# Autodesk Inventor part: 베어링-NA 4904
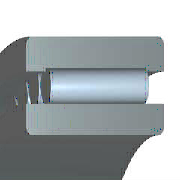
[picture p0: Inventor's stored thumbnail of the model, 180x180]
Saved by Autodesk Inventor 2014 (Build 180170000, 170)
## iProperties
IsCustomPart: 1
Company: 한국ATC센터
Created: 2009-02
Part Number: 베어링-NA 4904
Material: 강, 연강
Description: 니들 롤러 베어링 - 경계 치수 및 공차
Document SubType Name: Modeling
Standard: KS B 2029
Designer: KYOUNG IL JANG
Standards Organization: KS
Language: ko-KR
Size Designation: NA 4904 - 20 x 37 x 17
Categories: <MemberInstance><Categories><Category DisplayName="샤프트 부품" InternalName="7f7aeb1f-a693-4053-b835-cee3144e0d98" Mnemonic="SHFT"><Category DisplayName="베어링" Inter
Density: 7.86 g/cm^3
Mass: 73.0306 g
Surface Area: 90.2463 cm^2
Volume: 9.29143 cm^3
Vendor: CBT Solutions
Appearance: 강철
Author: KYOUNG IL JANG
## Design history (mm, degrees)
sketch "스케치"
  geometry: L1 (2.429, 16)-(14.571, 16); L2 (14.571, 16)-(14.571, 12.5); L3 (17, 12.5)-(0, 12.5); L4 (2.429, 12.5)-(2.429, 16); L5 (2.429, 14.25)-(14.571, 14.25); L6 (8.5, 14.25)-(8.5, 12.5); L7 (0, 10)-(17, 10); L8 (0, 18.5)-(17, 18.5); L9 (17, 10)-(17, 12.5); L10 (17, 15.65)-(17, 18.5); L11 (2.429, 15.65)-(0, 15.65); L12 (14.571, 15.65)-(17, 15.65); L13 (-6, 0)-(36, 0) reference; L14 (0, -1.9)-(0, 14.9) reference
  constraints: 24 end point, 8 point on line, 3 midpoint, 3 parallel, 3 perpendicular, 2 symmetric about line, 1 horizontal, 1 other
  dimensions: "d6" = 20 diameter of L7 L13 (= WD); "d7" = 25 diameter of L3 L13 (= KID1); "d8" = 37 diameter of L8 L13 (= BD); "d9" = 28.5 diameter of L6.start L13 (= 0.5 x WD + 0.5 x BD); "d10" = 31.3 diameter of L12 L13 (= 0.9 x BD + 0.9 x WD - 0.8 x KID1); "d11" = 32 diameter of L1 L13 (= BD + WD - KID1); "d12" = 2.42857 distance between parallel lines of L14 L4 (= 0.142857 x KB); "d13" = 17 distance between parallel lines of L14 L9 (= KB); "d14" = 14.57143 distance between parallel lines of L14 L2 (= 0.857143 x KB)
revolve "본체" stored, may be unused: angle "d17" = 90 deg
revolve "롤러" stored, may be unused: angle "d18" = 90 deg
pattern_circular "IDS_ARRAYROLLER[SIMPL:T]" dims angle "d2" = 360 deg
body "Solid1"
fillet "모깎기1" dims "d0" = 0.3 (= KRS)
other parameters: "WD" = 20 [user parameter; used in 6 equation terms], "BD" = 37 [user parameter; used in 6 equation terms], "KB" = 17 [user parameter; used in 3 equation terms], "KID1" = 25 [user parameter; used in 4 equation terms], "KRS" = 0.3 [user parameter; used in 1 equation term], "d3" = 0, "d4" = 0, "d5" = 0, "d15" = 0, "d16" = 0, "BC0" = 2.36e+07 [user parameter], "BBA" = 0 [user parameter], "BC" = 1.9e+07 [user parameter], "BR" = 18.5 (= 0.5 x BD) [user parameter]
